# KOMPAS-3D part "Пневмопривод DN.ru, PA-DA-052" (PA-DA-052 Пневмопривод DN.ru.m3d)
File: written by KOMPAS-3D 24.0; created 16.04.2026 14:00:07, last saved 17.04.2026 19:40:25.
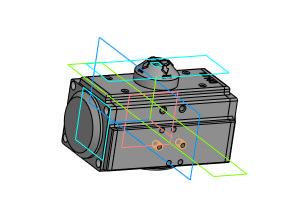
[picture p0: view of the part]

Document properties: Автор: DN.ru; Полное имя файла: C:\Работа\PA-DA-х Пневмопривод DN.ru\052\исходные материалы\PA-DA-052 Пневмопривод DN.ru.m3d

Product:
- Body: Тело 1  | qty 1
    Масса: 5.471999
- Body: Тело 2  | qty 1
    Масса: 5.471999
- Part/product: Пневмопривод DN.ru  | designation PA-DA-052
    Масса: 1.4
    Раздел спецификации: Прочие изделия
    Примечание: D290-00293

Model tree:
1. Эскиз:1
2. Элемент выдавливания:1
3. Эскиз:2  (with: Ребро.Элемент выдавливания:1)
4. Элемент выдавливания:2
5. Эскиз:3  (with: Ребро.Элемент выдавливания:2)
6. Элемент выдавливания:3  (with: Грань.Элемент выдавливания:2)
     Смещение 1 = -2; Расстояние 2 = 64; Смещение 2 = -2
7. Эскиз:4  (with: Грань.Элемент выдавливания:3, Ребро.Элемент выдавливания:3)
8. Элемент выдавливания:4
9. Эскиз:6  (with: Ребро.Элемент выдавливания:2)
10. Элемент выдавливания:6
11. Отверстие:2  (with: Грань.Элемент выдавливания:6)
     Глубина выреза = 10; Диаметр отверстия = 5; Угол конуса дна = 120; Расстояние 2 = 4
12. Массив по сетке:2  (with: Отверстие:2)  (3 pattern instances)
     Шаг 1 = 12; Угол раствора = 90; Шаг 2 = 32
13. Массив по сетке:3  (with: Отверстие:2)  (2 pattern instances)
     Шаг 1 = 32; Угол раствора = 90; Шаг 2 = 12
14. Отверстие:3  (with: Грань.Элемент выдавливания:6, Ребро.Элемент выдавливания:6)  (labels: W 1/4'')
     Глубина выреза = 10; Диаметр отверстия = 4.72357; Угол конуса дна = 120; Расстояние 1 = 12; Расстояние 2 = 20
15. W 1/4''  (with: Грань.Элемент выдавливания:6)  (labels: cil5_ex_DIN 477 BSW coarse)
     Длина резьбы = 8; Шаг резьбы = 1.27; Номинальный диаметр резьбы = 6.35
16. Массив по сетке:4  (with: Отверстие:3)  (labels: W 1/4'')  (2 pattern instances)
17. Эскиз:7  (with: Грань.Элемент выдавливания:2)
18. Элемент выдавливания:7
19. Эскиз:8  (with: Грань.Элемент выдавливания:2, Ребро.Элемент выдавливания:2)
20. Элемент выдавливания:8  (with: Грань.Элемент выдавливания:6)
     Расстояние 2 = 4
21. Отверстие:4  (with: Грань.Элемент выдавливания:2)
     Глубина выреза = 7; Диаметр отверстия = 5; Угол конуса дна = 118; Расстояние 1 = 6; Расстояние 2 = 10; Диаметр зенковки = 7; Глубина зенковки = 1; Угол зенковки = 90
22. Массив по сетке:5  (with: Отверстие:4)  (2 pattern instances)
     Шаг 1 = 20; Угол раствора = 90
23. Отверстие:5
     Глубина выреза = 10; Диаметр отверстия = 5; Угол конуса дна = 120; Диаметр зенковки = 7; Глубина зенковки = 1; Угол зенковки = 90
24. Массив по сетке:6  (with: Отверстие:5)  (4 pattern instances)
     Угол раствора = 90
25. Фаска:1  (with: Ребро.Элемент выдавливания:4)
     Угол = 45; Длина 1 = 10; Длина 2 = 10
26. Скругление:2  (with: Ребро.Элемент выдавливания:3)
     Радиус = 2
27. Скругление:3  (with: Ребро.Элемент выдавливания:6)
     Радиус = 2
28. Скругление:4  (with: Ребро.Элемент выдавливания:8, Ребро.Элемент выдавливания:2)
     Радиус = 2
29. Скругление:5  (with: Ребро.Элемент выдавливания:6)
     Радиус = 1
30. Смещенная плоскость:1
31. Эскиз:9
32. Элемент выдавливания:9  (with: Грань.Фаска:1)
     Расстояние 1 = 17.6642; Смещение 1 = 1
33. Смещенная плоскость:2
     Расстояние = 0.5
34. Эскиз:10
35. Элемент выдавливания:10
     Расстояние 1 = 10.9142
36. Эскиз:11
37. Элемент выдавливания:11
     Расстояние 1 = 1
38. Эскиз:12  (with: Грань.Элемент выдавливания:11)
39. Элемент выдавливания:12
     Расстояние 2 = 1
40. Эскиз:13  (with: Грань.Элемент выдавливания:11)
41. Элемент выдавливания:13
     Расстояние 2 = 1
42. Скругление:7  (with: Ребро.Элемент выдавливания:11)
     Радиус = 1
43. Скругление:8  (with: Ребро.Элемент выдавливания:8)
     Радиус = 2
44. Эскиз:14
45. Элемент выдавливания:14  (with: Грань.Фаска:1)
     Расстояние 1 = 29.1414; Смещение 1 = 0.1
46. Эскиз:15
47. Элемент выдавливания:15
     Расстояние 2 = 0.1
48. Отверстие:6  (with: Грань.Элемент выдавливания:2, Ребро.Элемент выдавливания:2)
     Глубина выреза = 10; Диаметр отверстия = 8; Угол конуса дна = 118; Расстояние 1 = 5; Расстояние 2 = 5
49. Зеркальный массив:1
50. Экземпляр ( 1 )
51. Экземпляр ( 2 )  (with: Отверстие:6)
52. Зеркальный массив:2  (with: Экземпляр ( 1 ), Экземпляр ( 2 ), Отверстие:6)
53. Зеркальный массив:3  (with: Экземпляр ( 1 ), Экземпляр ( 2 ), Зеркальный массив:2, Отверстие:6)
54. Зеркальный массив:4  (with: Экземпляр ( 1 ), Экземпляр ( 2 ), Зеркальный массив:1, Отверстие:6, Зеркальный массив:3, Зеркальный массив:2)
55. Фаска:2  (with: Ребро.Элемент выдавливания:7)
     Угол = 45; Длина 1 = 1; Длина 2 = 1
56. Фаска:3  (with: Ребро.Элемент выдавливания:1)
     Угол = 45; Длина 1 = 5; Длина 2 = 5
57. Смещенная плоскость:3  (with: Грань.Элемент выдавливания:1)
58. Эскиз:16
59. Элемент выдавливания:16
     Расстояние 2 = 0.1
60. Зеркальный массив:5  (with: Экземпляр ( 1 ), Экземпляр ( 2 ), Элемент выдавливания:16)

Expressions: H/2; -G/2; (E-C-1)/2
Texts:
  PA-DA-052
  GOST 26.020 Pr3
